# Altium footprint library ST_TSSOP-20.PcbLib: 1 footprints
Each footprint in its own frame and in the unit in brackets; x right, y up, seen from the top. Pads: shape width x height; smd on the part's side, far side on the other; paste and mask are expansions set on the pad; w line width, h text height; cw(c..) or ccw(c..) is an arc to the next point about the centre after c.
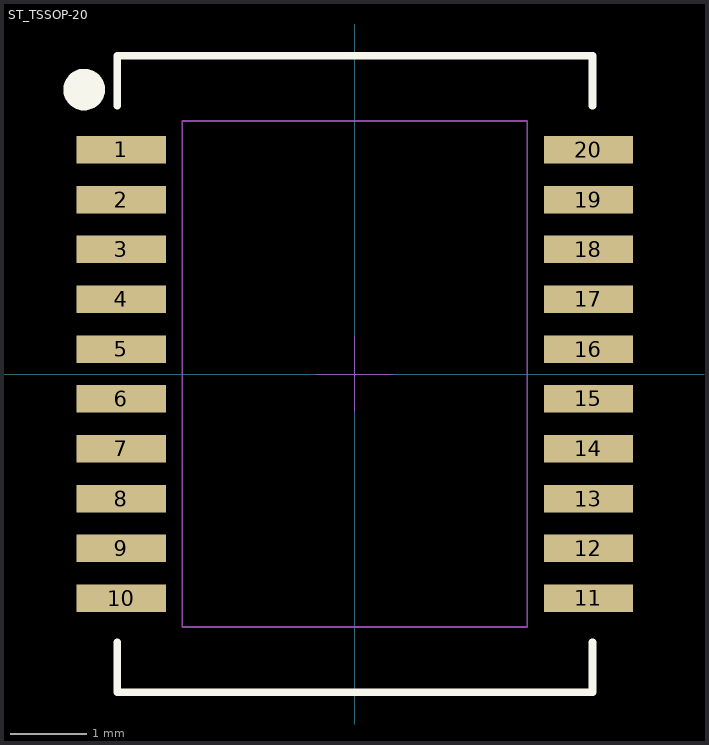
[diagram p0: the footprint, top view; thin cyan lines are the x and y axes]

## ST_TSSOP-20 [mm] "ST_TSSOP-20"
pads (20):
  rect 1.165x0.36 smd mask+0.025: 1(-3.047,2.925) 2(-3.047,2.275) 3(-3.047,1.625) 4(-3.047,0.975) 5(-3.047,0.325) 6(-3.047,-0.325) 7(-3.047,-0.975) 8(-3.047,-1.625) 9(-3.047,-2.275) 10(-3.047,-2.925) 11(3.047,-2.925) 12(3.047,-2.275) 13(3.047,-1.625) 14(3.047,-0.975) 15(3.047,-0.325) 16(3.047,0.325) 17(3.047,0.975) 18(3.047,1.625) 19(3.047,2.275) 20(3.047,2.925)
Top Overlay:
  circle w0.3: c-3.529,3.71 r0.121
  lines w0.1: -3.1,-3.5 -3.1,-4.15 3.1,-4.15 3.1,-3.5 ; -3.1,3.5 -3.1,4.15 3.1,4.15 3.1,3.5
Mechanical 5:
  text "1" at -3.978,2.825 h0.2
  text "10" at -4.137,-3.025 h0.2
  text "11" at 3.858,-3.025 h0.2
  text "15" at 3.858,-0.425 h0.2
  text "16" at 3.858,0.225 h0.2
  text "20" at 3.858,2.825 h0.2
  text "18" at 3.858,1.525 h0.2
  text "13" at 3.858,-1.725 h0.2
  text "3" at -3.978,1.525 h0.2
  text "8" at -3.978,-1.725 h0.2
  text "6" at -3.978,-0.425 h0.2
  text "2" at -3.978,2.175 h0.2
  text "4" at -3.978,0.875 h0.2
  text "7" at -3.978,-1.075 h0.2
  text "9" at -3.978,-2.375 h0.2
  text "19" at 3.858,2.175 h0.2
  text "17" at 3.858,0.875 h0.2
  text "14" at 3.858,-1.075 h0.2
  text "12" at 3.858,-2.375 h0.2
  text "5" at -3.978,0.225 h0.2
Mechanical 6:
  lines w0.025: -2.25,-3.3 2.25,-3.3 2.25,3.3 -2.25,3.3 -2.25,-3.3
Mechanical 7:
  lines w0.025: -2.25,-3.3 -2.25,3.3 2.25,3.3 2.25,-3.3 -2.25,-3.3
Mechanical 15:
  lines w0.001: -0.5,0 0.5,0 ; 0,-0.5 0,0.5
3D body: height 1.2, standoff 0.05, extent -2.25,-3.3 2.25,3.3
